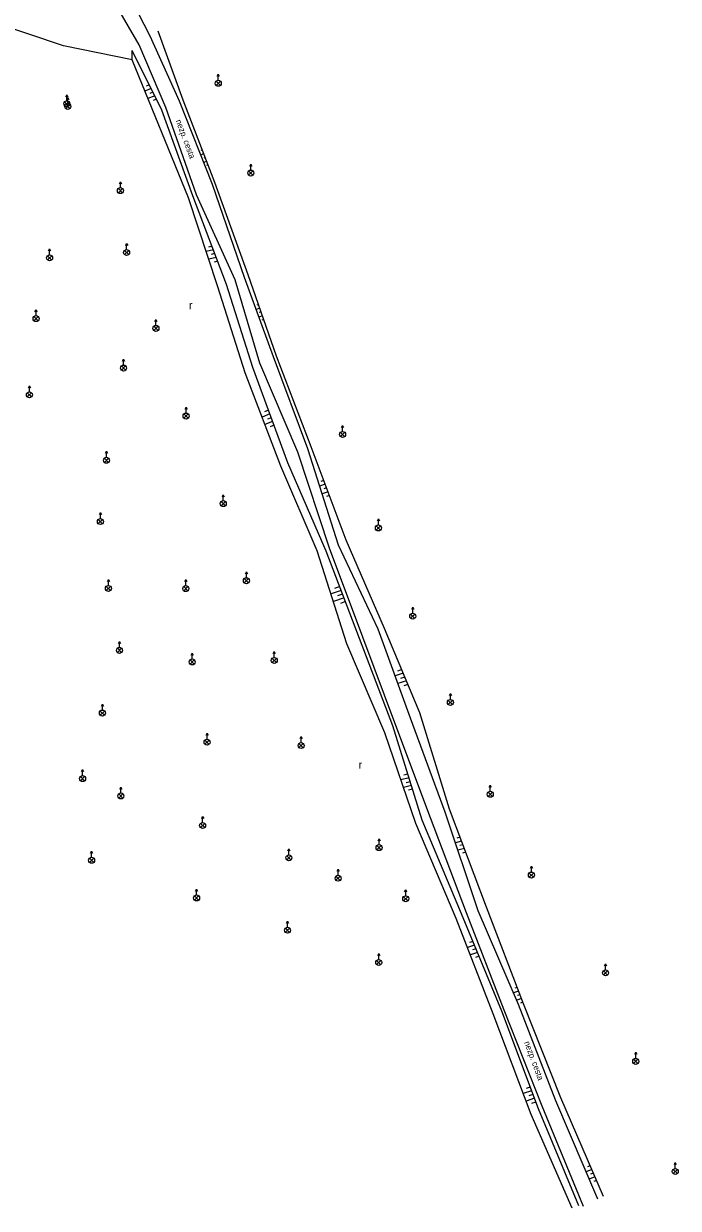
# Model space of a CAD drawing. Extents: x -639360 to -639196, y -1157339 to -1157085.
# Drawn here: x -639277.4 to -639195.6, y -1157339.1 to -1157191 of the extents above; entities that cross this region are included whole.
import ezdxf

# ---------------------------------------------------------------- set-up
doc = ezdxf.new("R2010")
doc.units = 0
for name, color, linetype in [('POMOC_POPIS', 7, 'Continuous'), ('ROZHRANÍ_PLOCH', 7, 'Continuous'), ('VÝŠKOPIS', 7, 'Continuous'), ('ZELEŇ', 7, 'Continuous'), ('ZN_BP', 7, 'Continuous'), ('ZN_KULTUR', 7, 'Continuous')]:
    doc.layers.add(name, color=color, linetype=linetype)

msp = doc.modelspace()

# ---------------------------------------------------------------- linework, layer by layer
at = {"layer": 'ROZHRANÍ_PLOCH'}
for points in [[(-639207.48, -1157338.86), (-639212.63, -1157326.34), (-639217.41, -1157314.31), (-639222.1, -1157302.14), (-639226.58, -1157290.28), (-639230.94, -1157278.76), (-639235.07, -1157267.69), (-639239.22, -1157256.58), (-639243.19, -1157244.58), (-639247.95, -1157233.47), (-639251.01, -1157223.03), (-639255.87, -1157212.42), (-639259.69, -1157201.48), (-639263.03, -1157193.67), (-639267.01, -1157186.76), (-639267.83, -1157185.31), (-639277.25, -1157185.48), (-639282.74, -1157184.98), (-639294.02, -1157181.84), (-639306.1, -1157178.69), (-639317.46, -1157175.03), (-639321.87, -1157173.53), (-639325.2, -1157171.55), (-639330.23, -1157170.89)], [(-639205.68, -1157337.95), (-639210.93, -1157325.66), (-639215.58, -1157313.63), (-639220.66, -1157301.89), (-639224.76, -1157289.56), (-639229.12, -1157277.82), (-639233.13, -1157266.71), (-639238.12, -1157256.22), (-639241.95, -1157244.15), (-639246.22, -1157232.66), (-639249.87, -1157222.73), (-639253.87, -1157211.12), (-639257.99, -1157200.71), (-639261.64, -1157192.58), (-639265.44, -1157185.18), (-639266.46, -1157183.69), (-639268.48, -1157178.89)]]:
    msp.add_lwpolyline(points, dxfattribs=at)
at = {"layer": 'VÝŠKOPIS'}
for p, q in [((-639261.51, -1157199.13), (-639262.3, -1157199.44)), ((-639261.73, -1157198.68), (-639262.15, -1157198.84)), ((-639261.29, -1157199.58), (-639261.7, -1157199.74)), ((-639261.06, -1157200.03), (-639261.93, -1157200.36)), ((-639260.84, -1157200.47), (-639261.26, -1157200.63)), ((-639255.11, -1157206.79), (-639255.3, -1157206.89)), ((-639254.93, -1157207.26), (-639255.32, -1157207.46)), ((-639254.57, -1157208.2), (-639254.95, -1157208.39)), ((-639254.75, -1157207.73), (-639254.94, -1157207.83)), ((-639254.39, -1157208.66), (-639254.58, -1157208.76)), ((-639253.91, -1157218.83), (-639254.37, -1157218.94)), ((-639253.73, -1157219.29), (-639254.64, -1157219.51)), ((-639253.38, -1157220.23), (-639254.32, -1157220.46)), ((-639253.56, -1157219.76), (-639254.02, -1157219.87)), ((-639253.2, -1157220.7), (-639253.66, -1157220.81)), ((-639248.1, -1157226.12), (-639248.32, -1157226.2)), ((-639247.94, -1157226.59), (-639248.39, -1157226.75)), ((-639247.61, -1157227.54), (-639248.05, -1157227.69)), ((-639247.77, -1157227.06), (-639248, -1157227.14)), ((-639247.45, -1157228.01), (-639247.67, -1157228.09)), ((-639246.85, -1157239.33), (-639247.33, -1157239.53)), ((-639246.68, -1157239.8), (-639247.65, -1157240.2)), ((-639246.33, -1157240.74), (-639247.29, -1157241.13)), ((-639246.5, -1157240.27), (-639246.99, -1157240.47)), ((-639246.16, -1157241.21), (-639246.64, -1157241.4)), ((-639239.94, -1157248.11), (-639240.3, -1157248.24)), ((-639239.77, -1157248.58), (-639240.47, -1157248.82)), ((-639239.41, -1157249.52), (-639240.16, -1157249.78)), ((-639239.59, -1157249.05), (-639239.95, -1157249.17)), ((-639239.24, -1157249.99), (-639239.6, -1157250.11)), ((-639237.94, -1157261.38), (-639238.58, -1157261.61)), ((-639237.76, -1157261.85), (-639239.02, -1157262.3)), ((-639237.41, -1157262.78), (-639238.72, -1157263.26)), ((-639237.59, -1157262.31), (-639238.23, -1157262.55)), ((-639237.23, -1157263.25), (-639237.87, -1157263.48)), ((-639230.19, -1157271.76), (-639230.72, -1157271.93)), ((-639230, -1157272.22), (-639231.02, -1157272.55)), ((-639229.62, -1157273.14), (-639230.68, -1157273.49)), ((-639229.81, -1157272.68), (-639230.33, -1157272.85)), ((-639229.43, -1157273.61), (-639229.95, -1157273.77)), ((-639229.28, -1157285.29), (-639230.29, -1157285.54)), ((-639229.43, -1157284.81), (-639229.93, -1157284.94)), ((-639228.98, -1157286.24), (-639229.97, -1157286.49)), ((-639229.13, -1157285.77), (-639229.63, -1157285.89)), ((-639228.83, -1157286.72), (-639229.33, -1157286.84)), ((-639222.9, -1157292.72), (-639223.29, -1157292.82)), ((-639222.73, -1157293.18), (-639223.49, -1157293.39)), ((-639222.37, -1157294.12), (-639223.17, -1157294.34)), ((-639222.55, -1157293.65), (-639222.94, -1157293.76)), ((-639222.2, -1157294.59), (-639222.59, -1157294.69)), ((-639221.09, -1157306.19), (-639221.98, -1157306.49)), ((-639221.28, -1157305.72), (-639221.73, -1157305.88)), ((-639220.71, -1157307.11), (-639221.62, -1157307.42)), ((-639220.9, -1157306.65), (-639221.35, -1157306.8)), ((-639220.52, -1157307.57), (-639220.97, -1157307.73)), ((-639215.58, -1157311.93), (-639216.22, -1157312.15)), ((-639215.75, -1157311.47), (-639216.07, -1157311.57)), ((-639215.22, -1157312.86), (-639215.82, -1157313.07)), ((-639215.4, -1157312.4), (-639215.71, -1157312.5)), ((-639215.04, -1157313.33), (-639215.35, -1157313.44)), ((-639214.14, -1157323.94), (-639214.65, -1157324.11)), ((-639213.96, -1157324.41), (-639215, -1157324.76)), ((-639213.61, -1157325.34), (-639214.64, -1157325.7)), ((-639213.79, -1157324.88), (-639214.3, -1157325.05)), ((-639213.44, -1157325.81), (-639213.96, -1157325.99)), ((-639206.44, -1157334.24), (-639207.15, -1157334.52)), ((-639206.64, -1157333.78), (-639206.99, -1157333.92)), ((-639206.04, -1157335.15), (-639206.75, -1157335.44)), ((-639206.24, -1157334.69), (-639206.6, -1157334.84)), ((-639205.84, -1157335.61), (-639206.2, -1157335.75))]:
    msp.add_line(p, q, dxfattribs=at)
for points in [[(-639204.98, -1157337.6), (-639210.32, -1157325.3), (-639214.96, -1157313.53), (-639219.61, -1157301.45), (-639224.23, -1157289.19), (-639227.95, -1157277.17), (-639232.33, -1157266.61), (-639237.14, -1157255.58), (-639241.51, -1157243.93), (-639245.87, -1157232.56), (-639249.38, -1157222.43), (-639253.55, -1157210.85), (-639257.5, -1157200.56), (-639260.66, -1157191.96)], [(-639263.89, -1157195.54), (-639263.88, -1157194.38)], [(-639208.06, -1157338.8), (-639213.12, -1157326.67), (-639217.67, -1157314.45), (-639222.71, -1157302.28), (-639227.63, -1157290.57), (-639231.31, -1157278.8), (-639235.48, -1157267.85), (-639239.63, -1157256.94), (-639244.42, -1157245.93), (-639248.81, -1157234), (-639252.09, -1157223.63), (-639256.3, -1157212.53), (-639260.17, -1157201.82), (-639263.88, -1157194.38)]]:
    msp.add_lwpolyline(points, dxfattribs=at)
at = {"layer": 'ZELEŇ'}
for points in [[(-639263.89, -1157195.54), (-639272.49, -1157193.78), (-639281.29, -1157190.84), (-639281.78, -1157186.88), (-639294.17, -1157183.32), (-639306.87, -1157180.07), (-639317.99, -1157176.5), (-639324.82, -1157174.77), (-639328.28, -1157173.85), (-639329.62, -1157175.35), (-639333.27, -1157189.37), (-639336.7, -1157202.86), (-639340.39, -1157216.72), (-639344.16, -1157230.08), (-639347.28, -1157242.28), (-639351.74, -1157255.63), (-639355.24, -1157269.24)], [(-639208.91, -1157339.09), (-639214.02, -1157327.35), (-639218.76, -1157314.78), (-639223.39, -1157302.86), (-639228.44, -1157290.98), (-639232.3, -1157279.65), (-639237.04, -1157268.52), (-639240.75, -1157256.9), (-639245.3, -1157246.34), (-639249.77, -1157234.65), (-639253.17, -1157223.93), (-639256.87, -1157212.79), (-639263.89, -1157195.54)]]:
    msp.add_lwpolyline(points, dxfattribs=at)
at = {"layer": 'ZN_BP'}
for p, q in [((-639253.13, -1157198.09), (-639253.13, -1157197.34)), ((-639253.4, -1157198.73), (-639252.87, -1157198.21)), ((-639252.87, -1157198.74), (-639253.4, -1157198.21)), ((-639272.33, -1157201.29), (-639271.8, -1157200.77)), ((-639271.8, -1157201.3), (-639272.33, -1157200.77)), ((-639272.2, -1157201.61), (-639271.68, -1157201.09)), ((-639271.68, -1157201.62), (-639272.2, -1157201.09)), ((-639272.06, -1157200.66), (-639272.06, -1157199.91)), ((-639271.94, -1157200.98), (-639271.94, -1157200.23)), ((-639249.33, -1157209.95), (-639248.8, -1157209.43)), ((-639248.8, -1157209.96), (-639249.33, -1157209.43)), ((-639249.06, -1157209.31), (-639249.06, -1157208.56)), ((-639265.36, -1157211.52), (-639265.36, -1157210.77)), ((-639265.62, -1157212.15), (-639265.1, -1157211.63)), ((-639265.1, -1157212.16), (-639265.62, -1157211.63)), ((-639264.58, -1157219.25), (-639264.58, -1157218.5)), ((-639274.47, -1157220.55), (-639273.95, -1157220.03)), ((-639273.95, -1157220.56), (-639274.47, -1157220.03)), ((-639274.21, -1157219.92), (-639274.21, -1157219.17)), ((-639264.84, -1157219.88), (-639264.32, -1157219.36)), ((-639264.32, -1157219.89), (-639264.84, -1157219.36)), ((-639276.18, -1157228.15), (-639275.65, -1157227.63)), ((-639275.65, -1157228.16), (-639276.18, -1157227.63)), ((-639275.91, -1157227.52), (-639275.91, -1157226.77)), ((-639261.19, -1157229.36), (-639260.66, -1157228.84)), ((-639260.66, -1157229.37), (-639261.19, -1157228.84)), ((-639260.92, -1157228.73), (-639260.92, -1157227.98)), ((-639264.97, -1157233.69), (-639264.97, -1157232.94)), ((-639265.23, -1157234.32), (-639264.71, -1157233.8)), ((-639264.71, -1157234.33), (-639265.23, -1157233.8)), ((-639276.74, -1157237.03), (-639276.74, -1157236.28)), ((-639277.01, -1157237.67), (-639276.48, -1157237.15)), ((-639276.48, -1157237.68), (-639277.01, -1157237.15)), ((-639257.15, -1157239.69), (-639257.15, -1157238.94)), ((-639257.42, -1157240.32), (-639256.89, -1157239.8)), ((-639256.89, -1157240.33), (-639257.42, -1157239.8)), ((-639237.85, -1157242.62), (-639237.33, -1157242.1)), ((-639237.33, -1157242.63), (-639237.85, -1157242.1)), ((-639237.59, -1157241.99), (-639237.59, -1157241.24)), ((-639267.36, -1157245.85), (-639266.84, -1157245.33)), ((-639266.84, -1157245.86), (-639267.36, -1157245.33)), ((-639267.1, -1157245.22), (-639267.1, -1157244.47)), ((-639252.5, -1157250.64), (-639252.5, -1157249.89)), ((-639252.77, -1157251.27), (-639252.24, -1157250.75)), ((-639252.24, -1157251.28), (-639252.77, -1157250.75)), ((-639267.87, -1157252.88), (-639267.87, -1157252.12)), ((-639233.12, -1157253.68), (-639233.12, -1157252.93)), ((-639268.14, -1157253.51), (-639267.61, -1157252.99)), ((-639267.61, -1157253.52), (-639268.14, -1157252.99)), ((-639233.39, -1157254.31), (-639232.86, -1157253.79)), ((-639232.86, -1157254.32), (-639233.39, -1157253.79)), ((-639249.62, -1157260.27), (-639249.62, -1157259.52)), ((-639267.14, -1157261.87), (-639266.61, -1157261.35)), ((-639266.61, -1157261.88), (-639267.14, -1157261.35)), ((-639266.87, -1157261.24), (-639266.87, -1157260.49)), ((-639257.45, -1157261.89), (-639256.93, -1157261.37)), ((-639256.93, -1157261.9), (-639257.45, -1157261.37)), ((-639257.19, -1157261.26), (-639257.19, -1157260.51)), ((-639249.89, -1157260.9), (-639249.36, -1157260.38)), ((-639249.36, -1157260.91), (-639249.89, -1157260.38)), ((-639228.82, -1157264.71), (-639228.82, -1157263.96)), ((-639229.08, -1157265.34), (-639228.56, -1157264.82)), ((-639228.56, -1157265.35), (-639229.08, -1157264.82)), ((-639265.74, -1157269.61), (-639265.22, -1157269.09)), ((-639265.22, -1157269.62), (-639265.74, -1157269.09)), ((-639265.48, -1157268.98), (-639265.48, -1157268.23)), ((-639256.66, -1157271.06), (-639256.13, -1157270.54)), ((-639256.13, -1157271.07), (-639256.66, -1157270.54)), ((-639256.39, -1157270.43), (-639256.39, -1157269.68)), ((-639246.4, -1157270.87), (-639245.87, -1157270.35)), ((-639245.87, -1157270.88), (-639246.4, -1157270.35)), ((-639246.13, -1157270.24), (-639246.13, -1157269.49)), ((-639224.11, -1157275.49), (-639224.11, -1157274.74)), ((-639267.62, -1157276.81), (-639267.62, -1157276.06)), ((-639224.38, -1157276.12), (-639223.85, -1157275.6)), ((-639223.85, -1157276.13), (-639224.38, -1157275.6)), ((-639267.89, -1157277.45), (-639267.36, -1157276.93)), ((-639267.36, -1157277.46), (-639267.89, -1157276.93)), ((-639254.8, -1157281.09), (-639254.27, -1157280.57)), ((-639254.27, -1157281.1), (-639254.8, -1157280.57)), ((-639254.53, -1157280.46), (-639254.53, -1157279.71)), ((-639243.04, -1157281.51), (-639242.51, -1157280.99)), ((-639242.51, -1157281.52), (-639243.04, -1157280.99)), ((-639242.77, -1157280.88), (-639242.77, -1157280.12)), ((-639270.35, -1157285.64), (-639269.83, -1157285.12)), ((-639269.83, -1157285.65), (-639270.35, -1157285.12)), ((-639270.09, -1157285.01), (-639270.09, -1157284.26)), ((-639265.3, -1157287.18), (-639265.3, -1157286.43)), ((-639219.13, -1157286.97), (-639219.13, -1157286.22)), ((-639265.57, -1157287.81), (-639265.04, -1157287.29)), ((-639265.04, -1157287.82), (-639265.57, -1157287.29)), ((-639219.4, -1157287.6), (-639218.87, -1157287.08)), ((-639218.87, -1157287.61), (-639219.4, -1157287.08)), ((-639255.34, -1157291.5), (-639254.82, -1157290.98)), ((-639254.82, -1157291.51), (-639255.34, -1157290.98)), ((-639255.08, -1157290.86), (-639255.08, -1157290.11)), ((-639233.03, -1157293.64), (-639233.03, -1157292.89)), ((-639244.3, -1157294.91), (-639244.3, -1157294.16)), ((-639233.3, -1157294.27), (-639232.77, -1157293.75)), ((-639232.77, -1157294.28), (-639233.3, -1157293.75)), ((-639269.22, -1157295.85), (-639268.7, -1157295.33)), ((-639268.7, -1157295.86), (-639269.22, -1157295.33)), ((-639268.96, -1157295.22), (-639268.96, -1157294.47)), ((-639244.57, -1157295.54), (-639244.04, -1157295.02)), ((-639244.04, -1157295.55), (-639244.57, -1157295.02)), ((-639238.15, -1157297.46), (-639238.15, -1157296.71)), ((-639214.26, -1157297.7), (-639213.73, -1157297.18)), ((-639213.73, -1157297.71), (-639214.26, -1157297.18)), ((-639213.99, -1157297.06), (-639213.99, -1157296.31)), ((-639238.42, -1157298.09), (-639237.89, -1157297.57)), ((-639237.89, -1157298.1), (-639238.42, -1157297.57)), ((-639256.1, -1157300.56), (-639255.58, -1157300.04)), ((-639255.58, -1157300.57), (-639256.1, -1157300.04)), ((-639255.84, -1157299.93), (-639255.84, -1157299.18)), ((-639229.96, -1157300.66), (-639229.44, -1157300.14)), ((-639229.44, -1157300.67), (-639229.96, -1157300.14)), ((-639229.7, -1157300.03), (-639229.7, -1157299.28)), ((-639244.47, -1157303.96), (-639244.47, -1157303.21)), ((-639244.73, -1157304.59), (-639244.21, -1157304.07)), ((-639244.21, -1157304.6), (-639244.73, -1157304.07)), ((-639233.07, -1157308), (-639233.07, -1157307.25)), ((-639233.33, -1157308.63), (-639232.81, -1157308.11)), ((-639232.81, -1157308.64), (-639233.33, -1157308.11)), ((-639204.72, -1157309.28), (-639204.72, -1157308.53)), ((-639204.98, -1157309.92), (-639204.46, -1157309.4)), ((-639204.46, -1157309.93), (-639204.98, -1157309.4)), ((-639201.21, -1157320.98), (-639200.69, -1157320.46)), ((-639200.69, -1157320.99), (-639201.21, -1157320.46)), ((-639200.95, -1157320.34), (-639200.95, -1157319.59)), ((-639196.27, -1157334.75), (-639195.74, -1157334.23)), ((-639195.74, -1157334.76), (-639196.27, -1157334.23)), ((-639196, -1157334.11), (-639196, -1157333.36))]:
    msp.add_line(p, q, dxfattribs=at)
for points in [[(-639253.26, -1157197.59), (-639253.13, -1157197.34), (-639253.01, -1157197.59)], [(-639272.19, -1157200.16), (-639272.06, -1157199.91), (-639271.94, -1157200.16)], [(-639272.07, -1157200.48), (-639271.94, -1157200.23), (-639271.82, -1157200.48)], [(-639249.19, -1157208.81), (-639249.06, -1157208.56), (-639248.94, -1157208.81)], [(-639265.48, -1157211.02), (-639265.36, -1157210.77), (-639265.23, -1157211.02)], [(-639264.7, -1157218.75), (-639264.58, -1157218.5), (-639264.45, -1157218.75)], [(-639274.33, -1157219.42), (-639274.21, -1157219.17), (-639274.08, -1157219.42)], [(-639276.04, -1157227.02), (-639275.91, -1157226.77), (-639275.79, -1157227.02)], [(-639261.05, -1157228.23), (-639260.92, -1157227.98), (-639260.8, -1157228.23)], [(-639265.09, -1157233.19), (-639264.97, -1157232.94), (-639264.84, -1157233.19)], [(-639276.86, -1157236.53), (-639276.74, -1157236.28), (-639276.61, -1157236.53)], [(-639257.28, -1157239.19), (-639257.15, -1157238.94), (-639257.03, -1157239.19)], [(-639237.71, -1157241.49), (-639237.59, -1157241.24), (-639237.46, -1157241.49)], [(-639267.22, -1157244.72), (-639267.1, -1157244.47), (-639266.97, -1157244.72)], [(-639252.62, -1157250.14), (-639252.5, -1157249.89), (-639252.38, -1157250.14)], [(-639267.99, -1157252.38), (-639267.87, -1157252.12), (-639267.74, -1157252.38)], [(-639233.24, -1157253.18), (-639233.12, -1157252.93), (-639232.99, -1157253.18)], [(-639249.74, -1157259.77), (-639249.62, -1157259.52), (-639249.49, -1157259.77)], [(-639266.99, -1157260.74), (-639266.87, -1157260.49), (-639266.74, -1157260.74)], [(-639257.32, -1157260.76), (-639257.19, -1157260.51), (-639257.07, -1157260.76)], [(-639228.95, -1157264.21), (-639228.82, -1157263.96), (-639228.7, -1157264.21)], [(-639265.6, -1157268.48), (-639265.48, -1157268.23), (-639265.35, -1157268.48)], [(-639256.52, -1157269.93), (-639256.39, -1157269.68), (-639256.27, -1157269.93)], [(-639246.26, -1157269.74), (-639246.13, -1157269.49), (-639246.01, -1157269.74)], [(-639224.23, -1157274.99), (-639224.11, -1157274.74), (-639223.98, -1157274.99)], [(-639267.74, -1157276.31), (-639267.62, -1157276.06), (-639267.49, -1157276.31)], [(-639254.66, -1157279.96), (-639254.53, -1157279.71), (-639254.41, -1157279.96)], [(-639242.9, -1157280.38), (-639242.77, -1157280.12), (-639242.65, -1157280.38)], [(-639270.21, -1157284.51), (-639270.09, -1157284.26), (-639269.96, -1157284.51)], [(-639265.43, -1157286.68), (-639265.3, -1157286.43), (-639265.18, -1157286.68)], [(-639219.26, -1157286.47), (-639219.13, -1157286.22), (-639219.01, -1157286.47)], [(-639255.2, -1157290.36), (-639255.08, -1157290.11), (-639254.95, -1157290.36)], [(-639233.16, -1157293.14), (-639233.03, -1157292.89), (-639232.91, -1157293.14)], [(-639244.43, -1157294.41), (-639244.3, -1157294.16), (-639244.18, -1157294.41)], [(-639269.08, -1157294.72), (-639268.96, -1157294.47), (-639268.83, -1157294.72)], [(-639238.28, -1157296.96), (-639238.15, -1157296.71), (-639238.03, -1157296.96)], [(-639214.11, -1157296.56), (-639213.99, -1157296.31), (-639213.86, -1157296.56)], [(-639255.96, -1157299.43), (-639255.84, -1157299.18), (-639255.71, -1157299.43)], [(-639229.83, -1157299.53), (-639229.7, -1157299.28), (-639229.58, -1157299.53)], [(-639244.59, -1157303.46), (-639244.47, -1157303.21), (-639244.34, -1157303.46)], [(-639233.2, -1157307.5), (-639233.07, -1157307.25), (-639232.95, -1157307.5)], [(-639204.84, -1157308.78), (-639204.72, -1157308.53), (-639204.59, -1157308.78)], [(-639201.08, -1157319.84), (-639200.95, -1157319.59), (-639200.83, -1157319.84)], [(-639196.12, -1157333.61), (-639196, -1157333.36), (-639195.88, -1157333.61)]]:
    msp.add_lwpolyline(points, dxfattribs=at)
for centre in [(-639253.13, -1157198.47), (-639272.06, -1157201.03), (-639271.94, -1157201.35), (-639249.06, -1157209.69), (-639265.36, -1157211.89), (-639274.21, -1157220.29), (-639264.58, -1157219.62), (-639275.91, -1157227.89), (-639260.92, -1157229.1), (-639264.97, -1157234.06), (-639276.74, -1157237.41), (-639257.15, -1157240.06), (-639237.59, -1157242.36), (-639267.1, -1157245.59), (-639252.5, -1157251.01), (-639267.87, -1157253.25), (-639233.12, -1157254.05), (-639249.62, -1157260.64), (-639266.87, -1157261.61), (-639257.19, -1157261.63), (-639228.82, -1157265.08), (-639265.48, -1157269.35), (-639256.39, -1157270.8), (-639246.13, -1157270.61), (-639224.11, -1157275.86), (-639267.62, -1157277.19), (-639254.53, -1157280.83), (-639242.77, -1157281.25), (-639270.09, -1157285.38), (-639219.13, -1157287.34), (-639265.3, -1157287.55), (-639255.08, -1157291.24), (-639233.03, -1157294.01), (-639268.96, -1157295.59), (-639244.3, -1157295.28), (-639213.99, -1157297.44), (-639238.15, -1157297.83), (-639255.84, -1157300.3), (-639229.7, -1157300.4), (-639244.47, -1157304.33), (-639233.07, -1157308.37), (-639204.72, -1157309.66), (-639200.95, -1157320.72), (-639196, -1157334.49)]:
    msp.add_circle(centre, 0.375, dxfattribs=at)

# ---------------------------------------------------------------- texts
at = {"layer": 'POMOC_POPIS'}
for rotation, p in [(290.4172, (-639258.46, -1157203.16)), (290.373, (-639214.9, -1157318.36))]:
    msp.add_text('nezp. cesta', height=0.75, rotation=rotation, dxfattribs=at).set_placement(p)
at = {"layer": 'ZN_KULTUR'}
for p in [(-639256.8, -1157226.71), (-639235.59, -1157284.15)]:
    msp.add_text('r', height=1, dxfattribs=at).set_placement(p)

doc.saveas('drawing.dxf')
